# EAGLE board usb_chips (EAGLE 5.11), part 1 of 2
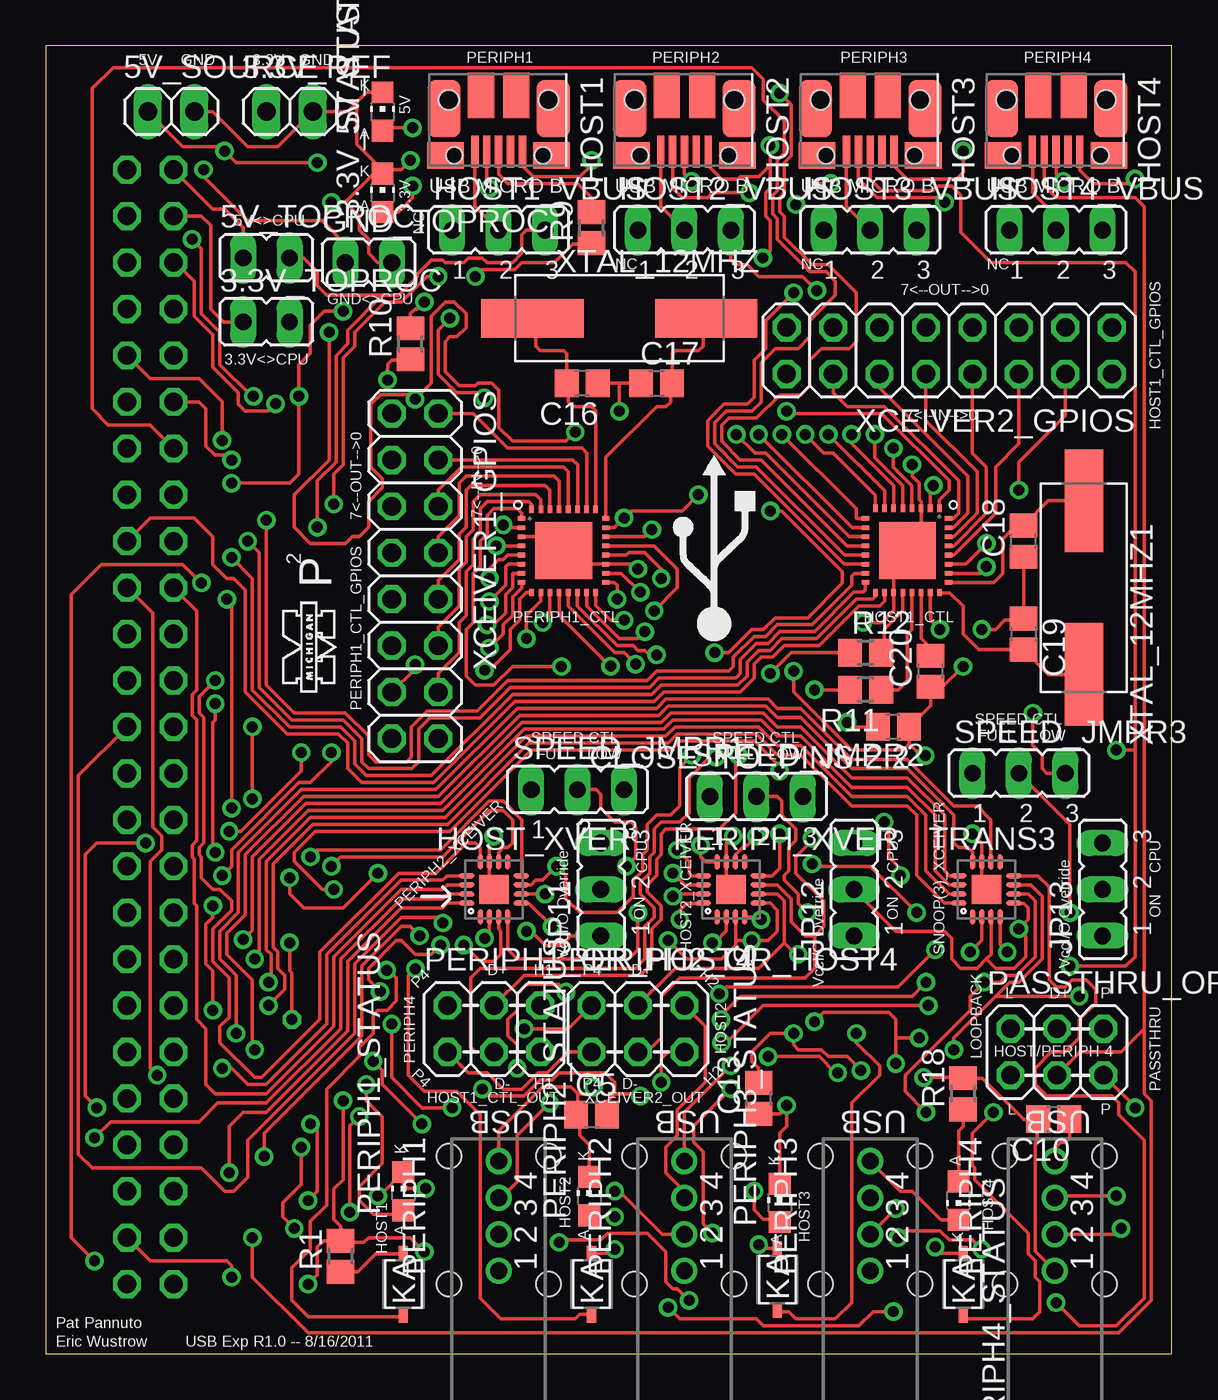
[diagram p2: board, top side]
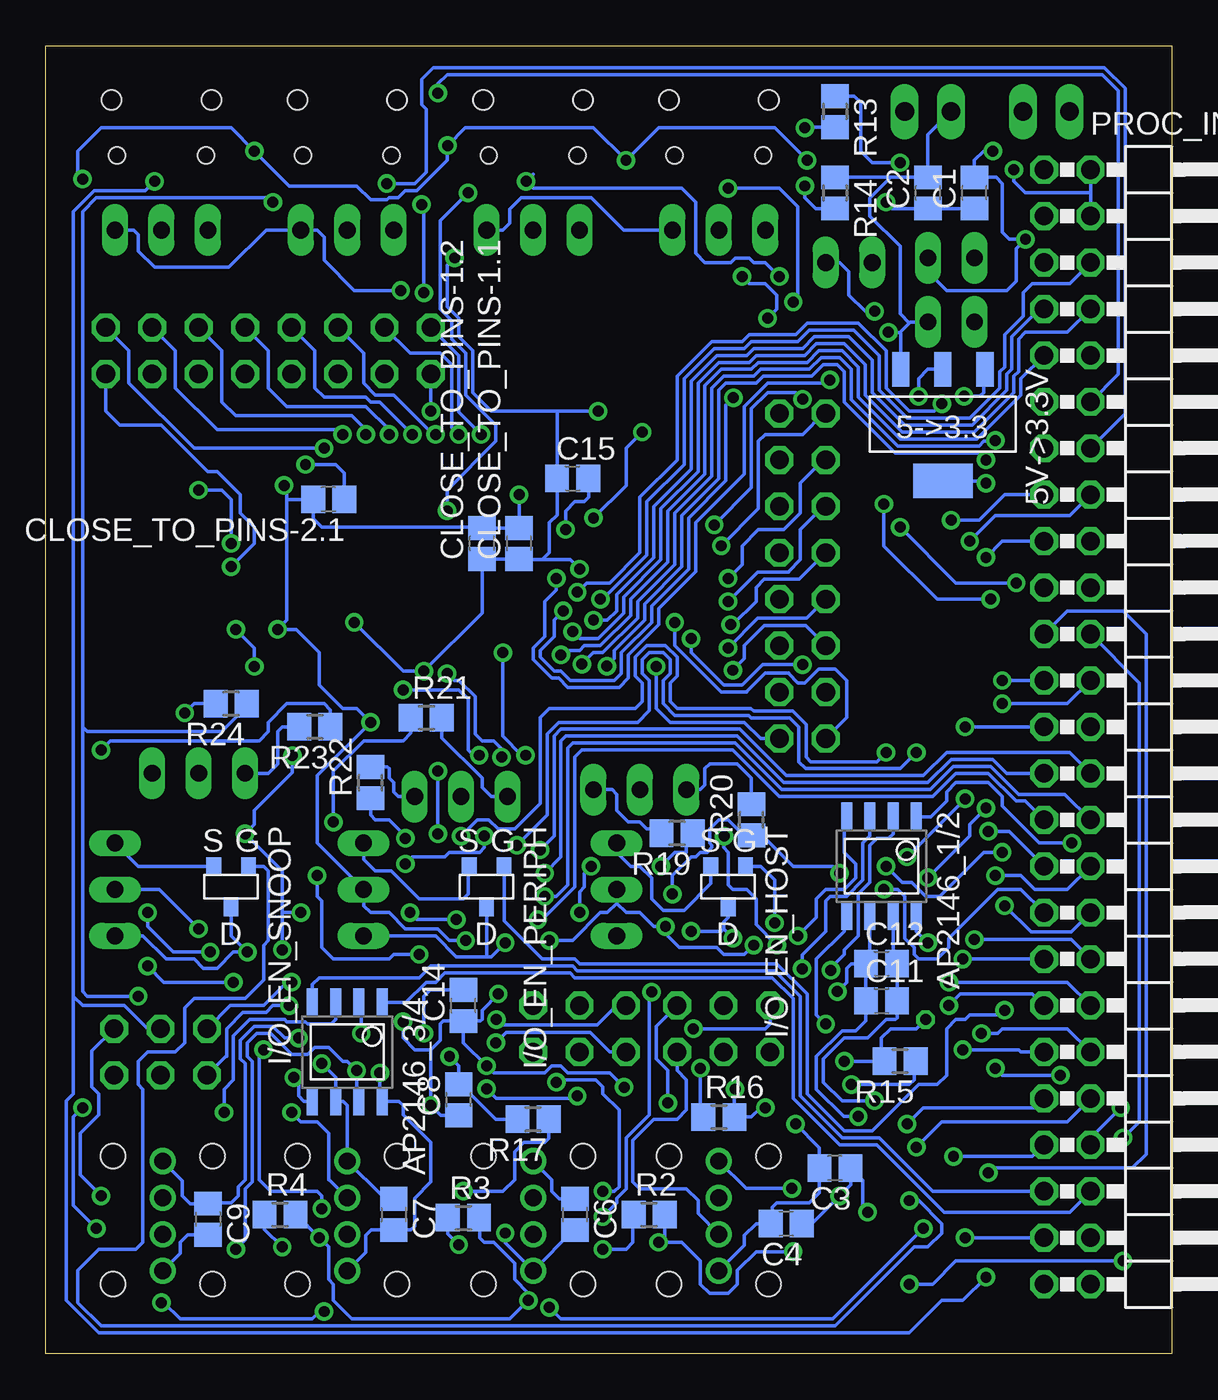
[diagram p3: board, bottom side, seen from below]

Size 61.57 x 71.55 mm. Coordinates in mm from the lower left corner, seen from the top.
Outline: 0,0 61.57,0 61.57,71.55 0,71.55 0,0
Copper layers (1*16): Top 0.035mm / dielectric 1.5mm / Bottom 0.035mm
Design rules "default *": minimum track width 7mil, minimum drill 16mil, track to track 7mil, track to pad 7mil, pad to pad 7mil, via to via 7mil, smd to smd 7mil, copper to edge 40mil, drill to drill 8mil, minimum pad ring 10mil, minimum via ring 8mil, stop-mask expansion 4mil, vias tented up to drill 0mil, thermal gap 10mil

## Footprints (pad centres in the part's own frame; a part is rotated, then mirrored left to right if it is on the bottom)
1X02 = drill 1.016 long: 1 -1.27,0; 2 1.27,0
CHIP-LED0805 = smd 1.2 x 1.2: A 0,-1.05; C 0,1.05
JP1 = drill 0.914 long: 1 0,-1.27; 2 0,1.27
MCP1825S = smd 0.95 x 1.9: GND 0,0; VIN -2.3,0; VOUT 2.3,0 | smd 3.25 x 1.9: GND_TAB 0,6.1
AP21X6 = smd 0.6 x 1.55: EN1 -1.905,-2.7; EN2 1.905,-2.7; FLG1 -0.635,-2.7; FLG2 0.635,-2.7; GND 0.635,2.7; IN -0.635,2.7; OUT1 -1.905,2.7; OUT2 1.905,2.7
C0805 = smd 1.3 x 1.5: 1 -0.85,0; 2 0.85,0
CMD28-21VRC = smd 0.8 x 0.5: A 1.7,0; K -1.7,0
USB_MICRO_B_FEMALE = smd 0.4 x 1.75: D+ 0,2.825; D- 0.65,2.825; GND -1.3,2.825; ID -0.65,2.825; VBUS 1.3,2.825 | smd 1.425 x 2.5: P$6 0.963,-0.25; P$7 -0.963,-0.25 | smd 2 x 1.46: P$8 2.9,3.03; P$9 -2.9,3.03 | smd 1.825 x 3.15: P$10 2.987,0.475; P$11 -2.987,0.475 | hole 0.904: 2.425,3.03; -2.425,3.03 | hole 1.081: 2.725,0; -2.725,0
MAX3421 = smd 0.25 x 0.4: P$1 -1.75,-2.3; P$2 -1.25,-2.3; P$3 -0.75,-2.3; P$4 -0.25,-2.3; P$5 0.25,-2.3; P$6 0.75,-2.3; P$7 1.25,-2.3; P$8 1.75,-2.3; P$17 1.75,2.3; P$18 1.25,2.3; P$19 0.75,2.3; P$20 0.25,2.3; P$21 -0.25,2.3; P$22 -0.75,2.3; P$23 -1.25,2.3; P$24 -1.75,2.3 | smd 0.4 x 0.25: P$9 2.3,-1.75; P$10 2.3,-1.25; P$11 2.3,-0.75; P$12 2.3,-0.25; P$13 2.3,0.25; P$14 2.3,0.75; P$15 2.3,1.25; P$16 2.3,1.75; P$25 -2.25,1.75; P$26 -2.25,1.25; P$27 -2.25,0.75; P$28 -2.25,0.25; P$29 -2.25,-0.25; P$30 -2.25,-0.75; P$31 -2.25,-1.25; P$32 -2.25,-1.75 | smd 3.1 x 3.1: P$33 0,0
JP2 = drill 0.914 long: 1 -2.54,0; 2 0,0; 3 2.54,0
S-PVQFN-N16 = smd 0.85 x 0.28: 1 -1.5,-0.75; 2 -1.5,-0.25; 3 -1.5,0.25; 4 -1.5,0.75; 9 1.5,0.75; 10 1.5,0.25; 11 1.5,-0.25; 12 1.5,-0.75 | smd 0.28 x 0.85: 5 -0.75,1.5; 6 -0.25,1.5; 7 0.25,1.5; 8 0.75,1.5; 13 0.75,-1.5; 14 0.25,-1.5; 15 -0.25,-1.5; 16 -0.75,-1.5 | smd 1.6 x 1.6: PAD 0,0
SOT-23_IRLML2060TRPBF = smd 0.802 x 0.972: D 0,2.256; G -0.95,0; S 0.95,0
2X03 = drill 1.016 octagon: 1 -2.54,-1.27; 2 -2.54,1.27; 3 0,-1.27; 4 0,1.27; 5 2.54,-1.27; 6 2.54,1.27
USB_A_FEMALE_VERT = drill 0.92 pad 1.2 round: D+ 0,4.73; D- 0,2.73; GND 0,6.73; VBUS 0,0.73 | hole 1.35: -2.72,7; 2.72,7; -2.72,0; 2.72,0
2X25/90 = drill 1.016 octagon: 1 -29.21,-6.35; 2 -29.21,-3.81; 3 -26.67,-6.35; 4 -26.67,-3.81; 5 -24.13,-6.35; 6 -24.13,-3.81; 7 -21.59,-6.35; 8 -21.59,-3.81; 9 -19.05,-6.35; 10 -19.05,-3.81; 11 -16.51,-6.35; 12 -16.51,-3.81; 13 -13.97,-6.35; 14 -13.97,-3.81; 15 -11.43,-6.35; 16 -11.43,-3.81; 17 -8.89,-6.35; 18 -8.89,-3.81; 19 -6.35,-6.35; 20 -6.35,-3.81; 21 -3.81,-6.35; 22 -3.81,-3.81; 23 -1.27,-6.35; 24 -1.27,-3.81; 25 1.27,-6.35; 26 1.27,-3.81; 27 3.81,-6.35; 28 3.81,-3.81; 29 6.35,-6.35; 30 6.35,-3.81; 31 8.89,-6.35; 32 8.89,-3.81; 33 11.43,-6.35; 34 11.43,-3.81; 35 13.97,-6.35; 36 13.97,-3.81; 37 16.51,-6.35; 38 16.51,-3.81; 39 19.05,-6.35; 40 19.05,-3.81; 41 21.59,-3.81; 42 21.59,-6.35; 43 24.13,-3.81; 44 24.13,-6.35; 45 26.67,-3.81; 46 26.67,-6.35; 47 29.21,-3.81; 48 29.21,-6.35; 49 31.75,-3.81; 50 31.75,-6.35
R0805 = smd 1.3 x 1.5: 1 -0.85,0; 2 0.85,0
2X08 = drill 1.016 octagon: 1 -8.89,-1.27; 2 -8.89,1.27; 3 -6.35,-1.27; 4 -6.35,1.27; 5 -3.81,-1.27; 6 -3.81,1.27; 7 -1.27,-1.27; 8 -1.27,1.27; 9 1.27,-1.27; 10 1.27,1.27; 11 3.81,-1.27; 12 3.81,1.27; 13 6.35,-1.27; 14 6.35,1.27; 15 8.89,-1.27; 16 8.89,1.27
ABLS_AT49_XTAL = smd 5.6 x 2.1: P$1 -4.75,0; P$2 4.75,0

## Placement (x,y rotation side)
3.3V_REF  [1X02]  13.34,67.94 0 top
3.3V_STATUS  BLUE_10mA  [CHIP-LED0805]  18.41,63.5 0 top
3.3V_TOPROC  [JP1]  12.07,56.44 270 top
5V->3.3V  MCP1825S  [MCP1825S]  12.52,53.85 180 bottom
5V_SOURCE  [1X02]  6.86,67.94 0 top
5V_STATUS  GREEN_10mA  [CHIP-LED0805]  18.41,67.94 0 top
5V_TOPROC  [JP1]  12.07,59.94 270 top
AP2146_1/2  AP21X6-SOP-8L  [AP21X6]  15.88,26.67 180 bottom
AP2146_3/4  AP21X6-SOP-8L  [AP21X6]  45.08,16.51 180 bottom
C1  4.7uF  [C0805]  10.79,63.5 90 bottom
C2  1.0uF  [C0805]  13.34,63.5 90 bottom
C3  68uF  [C0805]  18.41,10.16 180 bottom
C4  0.1uF  [C0805]  21.08,7.11 180 bottom
C5  0.1uF  [C0805]  29.85,13.08 0 top
C6  68uF  [C0805]  32.64,7.62 270 bottom
C7  68uF  [C0805]  42.54,7.62 270 bottom
C8  0.1uF  [C0805]  38.99,13.89 90 bottom
C9  0.1uF  [C0805]  52.7,7.37 270 bottom
C10  68uF  [C0805]  55.12,12.83 180 top
C11  0.1uF  [C0805]  15.88,19.3 0 bottom
C12  10uF  [C0805]  15.88,21.34 0 bottom
C13  0.1uF  [C0805]  38.99,13.97 90 top
C14  10uF  [C0805]  38.73,19.05 90 bottom
C15  1.0uF  [C0805]  32.77,47.88 0 bottom
C16  27pF  [C0805]  29.34,53.09 180 top
C17  27pF  [C0805]  33.4,53.09 0 top
C18  27pF  [C0805]  53.47,44.45 90 top
C19  27pF  [C0805]  53.47,39.37 270 top
C20  1.0uF  [C0805]  48.39,37.34 90 top
CLOSE_TO_PINS-1.1  0.1uF  [C0805]  35.69,44.32 90 bottom
CLOSE_TO_PINS-1.2  1.0uF  [C0805]  37.72,44.32 90 bottom
CLOSE_TO_PINS-2.1  0.1uF  [C0805]  46.1,46.74 180 bottom
CLOSE_TO_PINS-2.2  1.0uF  [C0805]  46.35,34.29 180 top
FAULT1  CMD28-21VRC  [CMD28-21VRC]  19.56,3.81 90 top
FAULT2  CMD28-21VRC  [CMD28-21VRC]  29.85,3.81 90 top
FAULT3  CMD28-21VRC  [CMD28-21VRC]  40,4.06 90 top
FAULT4  CMD28-21VRC  [CMD28-21VRC]  50.16,3.81 90 top
GND_TOPROC  [JP1]  17.65,59.69 270 top
HOST1  USB_MICRO_B_FEMALE  [USB_MICRO_B_FEMALE]  24.77,68.58 180 top
HOST1_CTL  MAX3421E  [MAX3421]  47.12,43.94 180 top
HOST1_VBUS  [JP2]  24.77,61.47 0 top
HOST2  USB_MICRO_B_FEMALE  [USB_MICRO_B_FEMALE]  34.92,68.58 180 top
HOST2_VBUS  [JP2]  34.92,61.47 0 top
HOST3  USB_MICRO_B_FEMALE  [USB_MICRO_B_FEMALE]  45.08,68.58 180 top
HOST3_VBUS  [JP2]  45.08,61.47 0 top
HOST4  USB_MICRO_B_FEMALE  [USB_MICRO_B_FEMALE]  55.24,68.58 180 top
HOST4_VBUS  [JP2]  55.24,61.47 0 top
HOST_XVER  TUSB2551A  [S-PVQFN-N16]  24.51,25.4 0 top
I/O_EN_HOST  IRLML2060TRPBF  [SOT-23_IRLML2060TRPBF]  24.26,26.67 180 bottom
I/O_EN_PERIPH  IRLML2060TRPBF  [SOT-23_IRLML2060TRPBF]  37.46,26.67 180 bottom
I/O_EN_SNOOP  IRLML2060TRPBF  [SOT-23_IRLML2060TRPBF]  51.43,26.67 180 bottom
JP11  I/O EN  [JP2]  30.35,25.4 90 top
JP12  I/O EN  [JP2]  44.2,25.4 90 top
JP13  I/O EN  [JP2]  57.78,25.4 90 top
PASSTHRU_OR_LOOPBACK  [2X03]  55.3,16.51 0 top
PERIPH1  USB_A_FEMALE_VERTFCI73725-0110  [USB_A_FEMALE_VERT]  24.77,3.81 0 top
PERIPH1_CTL  MAX3421E  [MAX3421]  28.32,43.94 270 top
PERIPH1_OR_HOST4  [2X03]  24.51,17.78 0 top
PERIPH1_STATUS  GREEN_5mA  [CHIP-LED0805]  19.56,8.89 0 top
PERIPH2  USB_A_FEMALE_VERTFCI73725-0110  [USB_A_FEMALE_VERT]  34.92,3.81 0 top
PERIPH2_OR_HOST4  [2X03]  32.38,17.78 0 top
PERIPH2_STATUS  GREEN_5mA  [CHIP-LED0805]  29.72,8.64 0 top
PERIPH3  USB_A_FEMALE_VERTFCI73725-0110  [USB_A_FEMALE_VERT]  45.08,3.81 0 top
PERIPH3_STATUS  GREEN_5mA  [CHIP-LED0805]  40.13,8.26 0 top
PERIPH4  USB_A_FEMALE_VERTFCI73725-0110  [USB_A_FEMALE_VERT]  55.18,3.81 0 top
PERIPH4_STATUS  GREEN_5mA  [CHIP-LED0805]  49.91,8.38 180 top
PERIPH_XVER  TUSB2551A  [S-PVQFN-N16]  37.46,25.4 0 top
PROC_INTERFACE  [2X25/90]  0.63,35.56 270 bottom
R1  10k  [R0805]  16.13,5.33 90 top
R2  10k  [R0805]  28.57,7.62 0 bottom
R3  10k  [R0805]  38.73,7.44 0 bottom
R4  10k  [R0805]  48.77,7.62 0 bottom
R9  33+/-1%  [R0805]  29.85,61.6 90 top
R10  33+/-1%  [R0805]  19.94,55.25 90 top
R11  33+/-1%  [R0805]  44.83,36.32 180 top
R12  33+/-1%  [R0805]  44.83,38.35 0 top
R13  500  [R0805]  18.41,67.94 270 bottom
R14  330  [R0805]  18.41,63.5 270 bottom
R15  1k  [R0805]  14.86,16 180 bottom
R16  1k  [R0805]  24.77,12.95 0 bottom
R17  1k  [R0805]  34.92,12.83 180 bottom
R18  1k  [R0805]  50.16,14.22 90 top
R19  1.5k+/-5%  [R0805]  27.05,28.47 180 bottom
R20  1.5k+/-5%  [R0805]  22.99,29.21 90 bottom
R21  1.5k+/-5%  [R0805]  40.77,34.8 0 bottom
R22  1.5k+/-5%  [R0805]  43.81,31.24 90 bottom
R23  1.5k+/-5%  [R0805]  46.86,34.29 180 bottom
R24  1.5k+/-5%  [R0805]  51.43,35.56 180 bottom
SPEED_JMPR1  12-High_23-Low  [JP2]  29.08,30.86 0 top
SPEED_JMPR2  12-High_23-Low  [JP2]  38.86,30.48 0 top
SPEED_JMPR3  12-High_23-Low  [JP2]  53.21,31.75 0 top
TRANS3  TUSB2551A  [S-PVQFN-N16]  51.43,25.4 0 top
XCEIVER1_GPIOS  [2X08]  20.19,42.55 270 top
XCEIVER2_GPIOS  [2X08]  49.4,54.86 180 top
XTAL_12MHZ  ABLS_AT49_XTAL  [ABLS_AT49_XTAL]  31.37,56.64 0 top
XTAL_12MHZ1  ABLS_AT49_XTAL  [ABLS_AT49_XTAL]  56.77,41.91 270 top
